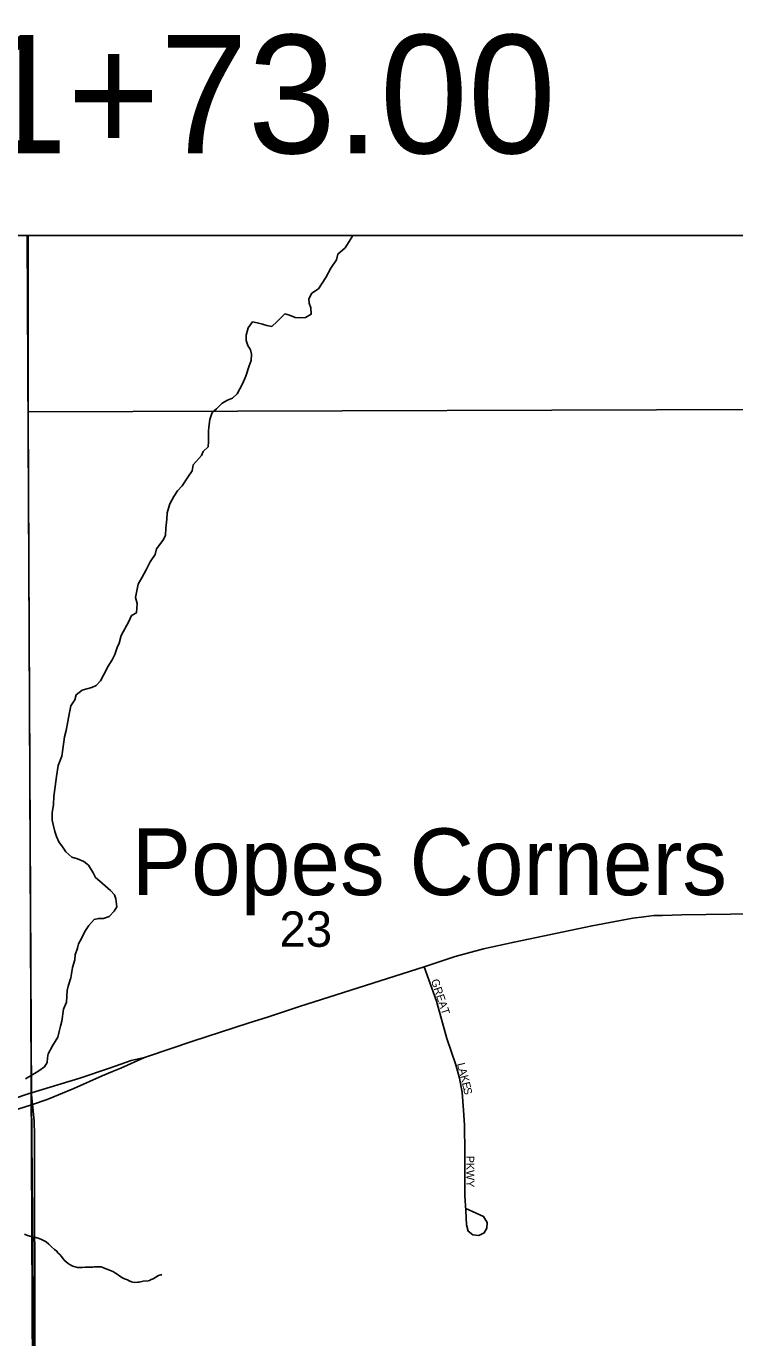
# Model space of a CAD drawing. Extents: x 10.6 to 44.6, y -2.6 to 23.4.
# Drawn here: x 15.273 to 16.111, y 17.696 to 19.247 of the extents above; entities that cross this region are included whole.
import ezdxf

# ---------------------------------------------------------------- set-up
doc = ezdxf.new("R2010")
doc.units = 0
for name, color, linetype in [('GM_X_Major_Lake', 7, 'Continuous'), ('GM_X_Major_River', 7, 'Continuous'), ('GM_X_Minor_River', 7, 'Continuous'), ('GM_X_Section', 7, 'Continuous'), ('GM_X_Section_Text', 7, 'Continuous'), ('GM_X_Township', 7, 'Continuous'), ('GM_X_Township_Road', 7, 'Continuous'), ('GM_X_Township_Subdivision', 7, 'Continuous'), ('GM_X_Township_Subdivision_Text', 7, 'Continuous'), ('GM_X_Unincorporated_Text', 7, 'Continuous'), ('GM_X_US_Route', 7, 'Continuous'), ('SH_Border', 7, 'Continuous'), ('SH_Text', 7, 'Continuous')]:
    doc.layers.add(name, color=color, linetype=linetype)

msp = doc.modelspace()

# ---------------------------------------------------------------- linework, layer by layer
at = {"layer": 'GM_X_Major_Lake'}
for points in [[(15.3826, 18.5174), (15.3849, 18.5265), (15.394, 18.5433), (15.397, 18.5501), (15.4031, 18.5535), (15.4035, 18.5589), (15.4038, 18.5646), (15.4019, 18.5714), (15.4038, 18.5813), (15.405, 18.5874), (15.4099, 18.5957), (15.4145, 18.6045), (15.4194, 18.6136), (15.4251, 18.6223), (15.4266, 18.6292), (15.4342, 18.6391), (15.4372, 18.6448), (15.4376, 18.6535), (15.4388, 18.6641), (15.4395, 18.6717), (15.4426, 18.6824), (15.4471, 18.6911), (15.4517, 18.6976), (15.457, 18.7037), (15.4638, 18.7139), (15.4688, 18.7215), (15.4703, 18.7284), (15.4798, 18.7394), (15.482, 18.7443), (15.4877, 18.7497), (15.4881, 18.7561), (15.4881, 18.7614), (15.4881, 18.7683), (15.4885, 18.7732), (15.49, 18.782), (15.4927, 18.7903), (15.4976, 18.7949), (15.5044, 18.8014), (15.5109, 18.8052), (15.5166, 18.8074), (15.5223, 18.8124), (15.5283, 18.8242), (15.5325, 18.8333), (15.5363, 18.8455), (15.5386, 18.8519), (15.539, 18.8595), (15.5378, 18.8645), (15.5348, 18.8698), (15.5329, 18.8755), (15.5329, 18.8819), (15.5352, 18.8907), (15.5405, 18.8975), (15.5458, 18.8964), (15.5523, 18.8949), (15.5572, 18.8933), (15.5633, 18.8922), (15.5693, 18.8979), (15.5784, 18.9071), (15.5841, 18.9055), (15.5906, 18.9029), (15.5959, 18.9025), (15.6031, 18.9029), (15.6096, 18.9067), (15.6092, 18.9143), (15.6073, 18.9196), (15.6069, 18.9249), (15.6103, 18.9314), (15.6183, 18.9367), (15.627, 18.95), (15.6331, 18.9611), (15.6395, 18.9709), (15.6414, 18.9778), (15.6498, 18.9854), (15.6547, 18.9926), (15.6589, 18.9996)], [(15.2717, 18.0022), (15.2823, 18.0086), (15.2876, 18.0117), (15.2944, 18.0166), (15.2975, 18.0216), (15.2978, 18.0269), (15.2986, 18.0318), (15.3039, 18.0413), (15.307, 18.0463), (15.31, 18.0516), (15.3115, 18.0584), (15.313, 18.0645), (15.3149, 18.0706), (15.3168, 18.0847), (15.3202, 18.093), (15.321, 18.1067), (15.3221, 18.112), (15.3256, 18.1215), (15.3263, 18.1265), (15.3275, 18.134), (15.3301, 18.1428), (15.3305, 18.1489), (15.3332, 18.1569), (15.3343, 18.1618), (15.3385, 18.169), (15.3419, 18.1766), (15.3468, 18.1835), (15.3529, 18.1907), (15.3582, 18.1918), (15.3639, 18.1918), (15.3707, 18.1941), (15.3768, 18.2006), (15.3798, 18.2055), (15.3787, 18.215), (15.3772, 18.22), (15.3723, 18.2249), (15.3662, 18.2306), (15.3597, 18.2359), (15.3544, 18.2405), (15.3518, 18.2458), (15.3465, 18.2549), (15.3408, 18.2594), (15.3332, 18.2625), (15.3267, 18.2643), (15.3195, 18.2708), (15.3154, 18.2765), (15.3112, 18.2826), (15.3085, 18.289), (15.3066, 18.2947), (15.3044, 18.3031), (15.3032, 18.308), (15.3032, 18.3167), (15.3048, 18.3266), (15.3051, 18.3361), (15.3086, 18.3597), (15.3105, 18.373), (15.3146, 18.384), (15.3173, 18.4007), (15.318, 18.4068), (15.3199, 18.4144), (15.3238, 18.4357), (15.3256, 18.4433), (15.3302, 18.4505), (15.3317, 18.4566), (15.3389, 18.4619), (15.3442, 18.4634), (15.3503, 18.465), (15.3552, 18.4676), (15.3606, 18.4729), (15.364, 18.4798), (15.3697, 18.4904), (15.3742, 18.4977), (15.3773, 18.5041), (15.3803, 18.5125), (15.3826, 18.5174)]]:
    msp.add_lwpolyline(points, dxfattribs=at)
at = {"layer": 'GM_X_Major_River'}
for points in [[(15.3826, 18.5174), (15.3849, 18.5265), (15.394, 18.5433), (15.397, 18.5501), (15.4031, 18.5535), (15.4035, 18.5589), (15.4038, 18.5646), (15.4019, 18.5714), (15.4038, 18.5813), (15.405, 18.5874), (15.4099, 18.5957), (15.4145, 18.6045), (15.4194, 18.6136), (15.4251, 18.6223), (15.4266, 18.6292), (15.4342, 18.6391), (15.4372, 18.6448), (15.4376, 18.6535), (15.4388, 18.6641), (15.4395, 18.6717), (15.4426, 18.6824), (15.4471, 18.6911), (15.4517, 18.6976), (15.457, 18.7037), (15.4638, 18.7139), (15.4688, 18.7215), (15.4703, 18.7284), (15.4798, 18.7394), (15.482, 18.7443), (15.4877, 18.7497), (15.4881, 18.7561), (15.4881, 18.7614), (15.4881, 18.7683), (15.4885, 18.7732), (15.49, 18.782), (15.4927, 18.7903), (15.4976, 18.7949), (15.5044, 18.8014), (15.5109, 18.8052), (15.5166, 18.8074), (15.5223, 18.8124), (15.5283, 18.8242), (15.5325, 18.8333), (15.5363, 18.8455), (15.5386, 18.8519), (15.539, 18.8595), (15.5378, 18.8645), (15.5348, 18.8698), (15.5329, 18.8755), (15.5329, 18.8819), (15.5352, 18.8907), (15.5405, 18.8975), (15.5458, 18.8964), (15.5523, 18.8949), (15.5572, 18.8933), (15.5633, 18.8922), (15.5693, 18.8979), (15.5784, 18.9071), (15.5841, 18.9055), (15.5906, 18.9029), (15.5959, 18.9025), (15.6031, 18.9029), (15.6096, 18.9067), (15.6092, 18.9143), (15.6073, 18.9196), (15.6069, 18.9249), (15.6103, 18.9314), (15.6183, 18.9367), (15.627, 18.95), (15.6331, 18.9611), (15.6395, 18.9709), (15.6414, 18.9778), (15.6498, 18.9854), (15.6547, 18.9926), (15.6589, 18.9996)], [(15.2717, 18.0022), (15.2823, 18.0086), (15.2876, 18.0117), (15.2944, 18.0166), (15.2975, 18.0216), (15.2978, 18.0269), (15.2986, 18.0318), (15.3039, 18.0413), (15.307, 18.0463), (15.31, 18.0516), (15.3115, 18.0584), (15.313, 18.0645), (15.3149, 18.0706), (15.3168, 18.0847), (15.3202, 18.093), (15.321, 18.1067), (15.3221, 18.112), (15.3256, 18.1215), (15.3263, 18.1265), (15.3275, 18.134), (15.3301, 18.1428), (15.3305, 18.1489), (15.3332, 18.1569), (15.3343, 18.1618), (15.3385, 18.169), (15.3419, 18.1766), (15.3468, 18.1835), (15.3529, 18.1907), (15.3582, 18.1918), (15.3639, 18.1918), (15.3707, 18.1941), (15.3768, 18.2006), (15.3798, 18.2055), (15.3787, 18.215), (15.3772, 18.22), (15.3723, 18.2249), (15.3662, 18.2306), (15.3597, 18.2359), (15.3544, 18.2405), (15.3518, 18.2458), (15.3465, 18.2549), (15.3408, 18.2594), (15.3332, 18.2625), (15.3267, 18.2643), (15.3195, 18.2708), (15.3154, 18.2765), (15.3112, 18.2826), (15.3085, 18.289), (15.3066, 18.2947), (15.3044, 18.3031), (15.3032, 18.308), (15.3032, 18.3167), (15.3048, 18.3266), (15.3051, 18.3361), (15.3086, 18.3597), (15.3105, 18.373), (15.3146, 18.384), (15.3173, 18.4007), (15.318, 18.4068), (15.3199, 18.4144), (15.3238, 18.4357), (15.3256, 18.4433), (15.3302, 18.4505), (15.3317, 18.4566), (15.3389, 18.4619), (15.3442, 18.4634), (15.3503, 18.465), (15.3552, 18.4676), (15.3606, 18.4729), (15.364, 18.4798), (15.3697, 18.4904), (15.3742, 18.4977), (15.3773, 18.5041), (15.3803, 18.5125), (15.3826, 18.5174)]]:
    msp.add_lwpolyline(points, dxfattribs=at)
at = {"layer": 'GM_X_Minor_River'}
msp.add_lwpolyline([(15.2706, 17.8184), (15.274, 17.8169), (15.2786, 17.8159), (15.2824, 17.8148), (15.2866, 17.8138), (15.2901, 17.8127), (15.2932, 17.8109), (15.2963, 17.8094), (15.2993, 17.8068), (15.3025, 17.8035), (15.306, 17.8005), (15.3087, 17.7983), (15.3102, 17.7964), (15.3126, 17.7942), (15.3141, 17.7923), (15.3157, 17.7905), (15.3176, 17.7878), (15.32, 17.7856), (15.3223, 17.7838), (15.3246, 17.7823), (15.3277, 17.7805), (15.3334, 17.7791), (15.3353, 17.7791), (15.3387, 17.7792), (15.3425, 17.7793), (15.3456, 17.7793), (15.3482, 17.7794), (15.3513, 17.7795), (15.3532, 17.7799), (15.3555, 17.7799), (15.3585, 17.78), (15.3612, 17.7797), (15.3631, 17.779), (15.3681, 17.7772), (15.3723, 17.7754), (15.3757, 17.7739), (15.3784, 17.7725), (15.3804, 17.771), (15.3835, 17.7688), (15.3865, 17.7669), (15.3889, 17.7655), (15.3923, 17.7644), (15.3946, 17.7633), (15.3973, 17.7622), (15.4004, 17.7615), (15.4045, 17.7616), (15.4064, 17.7617), (15.411, 17.7629), (15.4167, 17.7634), (15.4186, 17.7638), (15.4204, 17.765), (15.4227, 17.7658), (15.4261, 17.7678), (15.4291, 17.7694), (15.4317, 17.7702), (15.4329, 17.7702)], dxfattribs=at)
at = {"layer": 'GM_X_Section'}
msp.add_lwpolyline([(15.2738, 19.5646), (15.2731, 19.8042), (16.2385, 19.8158), (16.2657, 18.7944), (15.2751, 18.7912), (15.2749, 18.9996)], dxfattribs=at)
msp.add_lwpolyline([(15.2751, 18.7912), (16.2657, 18.7944), (16.2696, 17.6606), (15.2802, 17.6505)], close=True, dxfattribs=at)
at = {"layer": 'GM_X_Township'}
for points in [[(15.2903, 15.5267), (15.2954, 16.015), (15.2788, 17.979), (15.2737, 18.9996)], [(15.2737, 18.9996), (15.2788, 17.979), (15.2954, 16.015), (15.2903, 15.5267)]]:
    msp.add_lwpolyline(points, dxfattribs=at)
at = {"layer": 'GM_X_Township_Road'}
msp.add_lwpolyline([(15.2837, 17.2802), (15.2834, 17.4331), (15.2825, 17.935), (15.282, 17.9525), (15.28, 17.9719), (15.2788, 17.9838), (15.2786, 17.9856)], dxfattribs=at)
at = {"layer": 'GM_X_Township_Subdivision'}
msp.add_lwpolyline([(15.7433, 18.1346), (15.7579, 18.094), (15.7703, 18.0501), (15.7807, 18.0189), (15.785, 18.0032), (15.7885, 17.9861), (15.7901, 17.965), (15.7912, 17.9474), (15.7915, 17.9151), (15.7915, 17.8639), (15.7928, 17.8465), (15.7934, 17.8294), (15.7953, 17.8219), (15.801, 17.8175), (15.808, 17.817), (15.8145, 17.82), (15.8175, 17.8254), (15.8178, 17.8324), (15.8137, 17.8392), (15.8048, 17.8435), (15.7927, 17.8487)], dxfattribs=at)
at = {"layer": 'GM_X_US_Route'}
for points in [[(15.5351, 18.068), (15.5591, 18.0757), (15.5958, 18.0877), (15.7433, 18.1346), (15.7802, 18.1468), (15.8136, 18.1561), (15.8498, 18.1639), (15.9421, 18.1834), (15.9903, 18.1922), (16.0032, 18.1939), (16.0152, 18.1954), (16.0252, 18.1954), (16.0481, 18.1961), (16.1058, 18.1971), (16.1664, 18.1976), (16.2763, 18.1986), (16.3193, 18.1995), (16.4011, 18.2003), (16.4775, 18.2012)], [(15.3748, 18.011), (15.3844, 18.015), (15.4124, 18.0274), (15.416, 18.0288), (15.4697, 18.0469), (15.5351, 18.068)], [(15.254, 17.9775), (15.2786, 17.9856), (15.2786, 17.9856), (15.2788, 17.9856), (15.3361, 18.003), (15.3711, 18.0148), (15.3966, 18.0238), (15.4124, 18.0274)], [(14.625, 17.9478), (14.772, 17.9466), (14.8369, 17.9462), (14.9376, 17.9449), (15.0268, 17.9438), (15.1031, 17.9434), (15.1323, 17.944), (15.1569, 17.9455), (15.1842, 17.9492), (15.2118, 17.9539), (15.236, 17.9591), (15.2554, 17.9641), (15.2789, 17.9715), (15.28, 17.9719), (15.2973, 17.9777), (15.3291, 17.9908), (15.3623, 18.0058), (15.3748, 18.011)]]:
    msp.add_lwpolyline(points, dxfattribs=at)
at = {"layer": 'SH_Border'}
msp.add_lwpolyline([(14.506, 19.5646), (16.2314, 19.5646), (16.2314, 18.9996), (14.506, 18.9996)], close=True, dxfattribs=at)

# ---------------------------------------------------------------- texts
at = {"layer": 'GM_X_Section_Text'}
msp.add_text('23', height=0.04186, rotation=0, dxfattribs=at).set_placement((15.5722, 18.1584))
at = {"layer": 'GM_X_Township_Subdivision_Text'}
for s, rotation, p in [('GREAT', 288.4379, (15.7513, 18.1185)), ('L', 283.9899, (15.7822, 18.02)), ('A', 283.9726, (15.7838, 18.0135)), ('K', 283.9904, (15.7859, 18.0054)), ('E', 283.9899, (15.7879, 17.9973)), ('S', 281.61, (15.7895, 17.991)), ('PKWY', 270, (15.7931, 17.9112))]:
    msp.add_text(s, height=0.00947, rotation=rotation, dxfattribs=at).set_placement(p)
at = {"layer": 'GM_X_Unincorporated_Text'}
msp.add_text('Popes Corners', height=0.078977, rotation=0, dxfattribs=at).set_placement((15.3972, 18.2195))
at = {"layer": 'SH_Text'}
msp.add_text('STA 631+73.00', height=0.14, dxfattribs=at).set_placement((14.5929, 19.0971))

doc.saveas('drawing.dxf')
